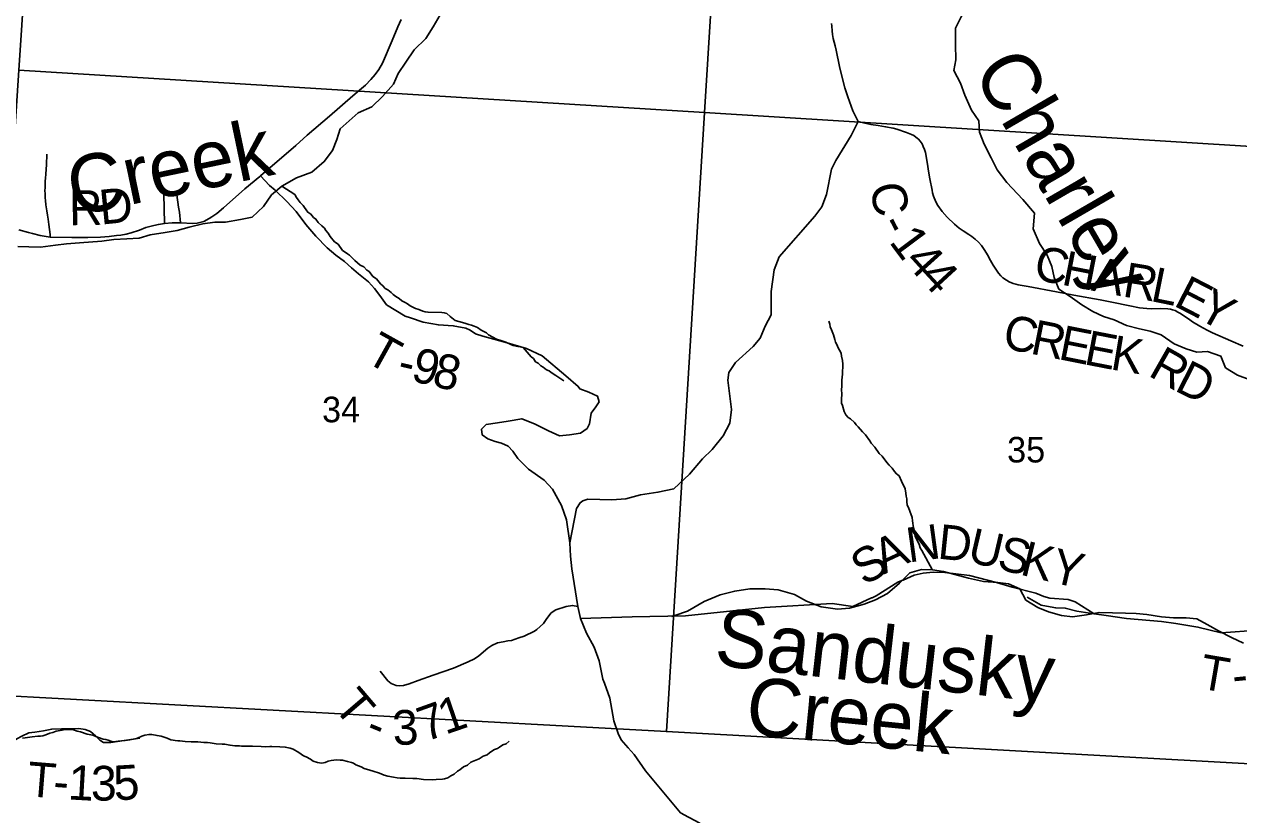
# Model space of a CAD drawing. Extents: x 0 to 45.4, y -2.2 to 22.
# Drawn here: x 5.991 to 7.977, y 14.939 to 16.232 of the extents above; entities that cross this region are included whole.
import ezdxf

# ---------------------------------------------------------------- set-up
doc = ezdxf.new("R2010")
doc.units = 0
for name, color, linetype in [('GM_X_Corporation', 7, 'Continuous'), ('GM_X_County_Road', 7, 'Continuous'), ('GM_X_County_Road_Text', 7, 'Continuous'), ('GM_X_Minor_River', 7, 'Continuous'), ('GM_X_Minor_River_Text', 7, 'Continuous'), ('GM_X_Section_Text', 7, 'Continuous'), ('GM_X_Township_Road', 7, 'Continuous'), ('GM_X_Township_Road_Text', 7, 'Continuous')]:
    doc.layers.add(name, color=color, linetype=linetype)

msp = doc.modelspace()

# ---------------------------------------------------------------- linework, layer by layer
at = {"layer": 'GM_X_Corporation'}
for points in [[(7.1661, 17.098), (7.1036, 16.0876), (5.9818, 16.1569), (6.0488, 17.1677)], [(8.2701, 17.0306), (8.2164, 16.0186), (7.1036, 16.0876), (7.1661, 17.098)], [(5.9818, 16.1569), (7.1036, 16.0876), (7.0412, 15.0748), (5.9148, 15.1362)], [(7.1036, 16.0876), (8.2164, 16.0186), (8.1634, 15.0131), (7.0412, 15.0748)]]:
    msp.add_lwpolyline(points, close=True, dxfattribs=at)
at = {"layer": 'GM_X_County_Road'}
for points in [[(6.2975, 15.9171), (6.3056, 15.9228), (6.3168, 15.9317), (6.3514, 15.9628), (6.3761, 15.9833), (6.3771, 15.9842), (6.4348, 16.0336), (6.4533, 16.0505), (6.4903, 16.082), (6.5283, 16.1148), (6.5393, 16.1242), (6.5488, 16.1326), (6.5575, 16.1417), (6.5646, 16.1498), (6.5707, 16.1582), (6.5766, 16.1686), (6.5927, 16.2054), (6.602, 16.228), (6.6071, 16.24)], [(7.3546, 16.0733), (7.346, 16.0904), (7.3377, 16.1136), (7.333, 16.1284), (7.3286, 16.1453), (7.3244, 16.1628), (7.3185, 16.1899), (7.317, 16.1971), (7.3141, 16.2086), (7.3129, 16.2154), (7.3123, 16.2215), (7.3117, 16.2292), (7.3111, 16.2332)], [(6.9396, 15.1541), (6.9373, 15.1605), (6.9313, 15.1908), (6.9232, 15.2131), (6.9105, 15.2359), (6.9004, 15.2597), (6.896, 15.2794), (6.8867, 15.3412), (6.884, 15.3617), (6.883, 15.3839), (6.8943, 15.4397), (6.9003, 15.4493), (6.9046, 15.4523), (6.9126, 15.455), (6.9516, 15.4543), (6.9748, 15.4558), (6.9989, 15.4624), (7.0273, 15.4666), (7.053, 15.4719), (7.0788, 15.4962), (7.1, 15.5209), (7.1159, 15.5364), (7.1341, 15.5588), (7.1447, 15.5793), (7.1478, 15.6021), (7.1417, 15.65), (7.1432, 15.6622), (7.1542, 15.6789), (7.183, 15.7051), (7.1943, 15.7188), (7.2027, 15.7382), (7.2122, 15.7568), (7.2122, 15.7948), (7.2171, 15.8305), (7.2258, 15.8514), (7.2837, 15.9181), (7.2952, 15.9337), (7.303, 15.9535), (7.3113, 15.9951), (7.3181, 16.0092), (7.3432, 16.0501), (7.3546, 16.0733)], [(7.3546, 16.0733), (7.3636, 16.0708), (7.3755, 16.068), (7.3875, 16.0665), (7.3997, 16.0645), (7.4121, 16.0621), (7.4181, 16.0605), (7.4339, 16.0553), (7.4417, 16.052), (7.4457, 16.05), (7.4492, 16.0474), (7.4532, 16.0441), (7.4561, 16.0409), (7.4596, 16.0363), (7.4613, 16.0324), (7.4635, 16.0272), (7.4649, 16.0223), (7.4681, 16.0032), (7.4699, 15.9918), (7.472, 15.9791), (7.4755, 15.9608), (7.4765, 15.9566), (7.478, 15.9509), (7.4818, 15.9417), (7.4851, 15.9355), (7.4921, 15.9259), (7.5004, 15.9165), (7.5121, 15.9051), (7.52, 15.8986), (7.5263, 15.8944), (7.5357, 15.8881), (7.5408, 15.8847), (7.5463, 15.8804), (7.5514, 15.8755), (7.5566, 15.8703), (7.562, 15.8621), (7.566, 15.8547), (7.5712, 15.8459), (7.5758, 15.8381), (7.5798, 15.8313), (7.5845, 15.8247), (7.5882, 15.8207), (7.5915, 15.8174)], [(5.9819, 15.8958), (5.9976, 15.8914), (6.0044, 15.8896), (6.0167, 15.8865), (6.0334, 15.8838), (6.0685, 15.8831), (6.0781, 15.8831), (6.0951, 15.8835), (6.1153, 15.884), (6.1299, 15.8851), (6.1417, 15.8863), (6.1489, 15.8873), (6.1573, 15.8889), (6.1658, 15.891), (6.1791, 15.8954), (6.1898, 15.8995), (6.196, 15.9012), (6.2029, 15.9029), (6.2104, 15.9046), (6.2204, 15.9061), (6.233, 15.9074), (6.2465, 15.9072), (6.2665, 15.9063), (6.2736, 15.9067), (6.2846, 15.9094), (6.2935, 15.9142), (6.2975, 15.9171)], [(7.5915, 15.8174), (7.5976, 15.8133), (7.6019, 15.8106), (7.608, 15.8082), (7.6128, 15.807)], [(7.6128, 15.807), (7.6166, 15.806), (7.633, 15.803), (7.6793, 15.7943), (7.7074, 15.7892), (7.7505, 15.7813), (7.7696, 15.7777), (7.7993, 15.7715), (7.8147, 15.7683), (7.8268, 15.7671), (7.8346, 15.7668), (7.8494, 15.767), (7.8611, 15.7666), (7.8656, 15.7661), (7.869, 15.7652), (7.8734, 15.7637), (7.8778, 15.7614), (7.882, 15.7587), (7.897, 15.7486), (7.9018, 15.7454), (7.9138, 15.7383), (7.9258, 15.7316), (7.9343, 15.7274), (7.9644, 15.7141), (7.9844, 15.7055)], [(7.2323, 14.6533), (7.2219, 14.6911), (7.2115, 14.7136), (7.1903, 14.7423), (7.169, 14.7705), (7.1488, 14.7944), (7.1219, 14.8551), (7.1121, 14.8973), (7.109, 14.909), (7.1011, 14.9216), (7.0886, 14.9288), (7.0772, 14.9349), (7.064, 14.9421), (7.0068, 15.0105), (6.9882, 15.0375), (6.9785, 15.0483), (6.9672, 15.0617), (6.9622, 15.0719), (6.9553, 15.0924), (6.9485, 15.1296), (6.9396, 15.1541)]]:
    msp.add_lwpolyline(points, dxfattribs=at)
at = {"layer": 'GM_X_Minor_River'}
for points in [[(7.5145, 16.1739), (7.5139, 16.199), (7.514, 16.2256), (7.5239, 16.2453), (7.5346, 16.2628), (7.5399, 16.2833), (7.5423, 16.3023), (7.5469, 16.3236), (7.5538, 16.3418), (7.544, 16.3601), (7.5267, 16.3724), (7.5085, 16.3884), (7.4912, 16.3999), (7.4753, 16.4144)], [(5.9803, 15.8686), (5.9985, 15.8678), (6.0174, 15.8677), (6.0417, 15.8706), (6.0599, 15.8729), (6.0811, 15.8743), (6.1175, 15.8772), (6.1372, 15.8802), (6.1584, 15.8809), (6.1788, 15.8823), (6.197, 15.8876), (6.2213, 15.8913), (6.241, 15.895), (6.2607, 15.9002), (6.2827, 15.9055), (6.3024, 15.9084), (6.3198, 15.9084), (6.3448, 15.9129), (6.3638, 15.9166), (6.382, 15.934), (6.395, 15.953), (6.4124, 15.9673), (6.436, 15.9809), (6.461, 15.99), (6.4815, 16.0074), (6.4952, 16.0256), (6.5021, 16.0438), (6.5075, 16.0613), (6.5371, 16.087), (6.5591, 16.0968), (6.5766, 16.1142), (6.5949, 16.1339), (6.6025, 16.1514), (6.6147, 16.1704), (6.6284, 16.1901), (6.6475, 16.209), (6.6596, 16.228), (6.6711, 16.2477)], [(7.9941, 15.6511), (7.9752, 15.658), (7.9556, 15.6703), (7.9481, 15.6893), (7.9261, 15.697), (7.9087, 15.6955), (7.8913, 15.7009), (7.8717, 15.7094), (7.8505, 15.7239), (7.8324, 15.73), (7.815, 15.7339), (7.7938, 15.7393), (7.7734, 15.7485), (7.756, 15.7539), (7.7386, 15.7623), (7.7204, 15.7731), (7.7016, 15.7868), (7.6827, 15.799), (7.6752, 15.8181), (7.6715, 15.8356), (7.664, 15.8546), (7.6512, 15.8737), (7.6407, 15.8973), (7.643, 15.9231), (7.6242, 15.9453), (7.5978, 15.9735), (7.582, 15.9941), (7.5722, 16.0139), (7.5609, 16.036), (7.5534, 16.0558), (7.552, 16.0741), (7.5399, 16.0916), (7.5294, 16.116), (7.5219, 16.1358), (7.5114, 16.1564), (7.5145, 16.1739)], [(6.4124, 15.9673), (6.4335, 15.9536), (6.436, 15.949), (6.439, 15.9448), (6.4423, 15.9405), (6.4468, 15.9359), (6.4494, 15.9324), (6.4546, 15.9247), (6.4598, 15.9216), (6.4642, 15.9158), (6.468, 15.9135), (6.4717, 15.9077), (6.4776, 15.9023), (6.4817, 15.8984), (6.484, 15.895), (6.488, 15.8903), (6.4914, 15.8849), (6.4984, 15.8761), (6.504, 15.8722), (6.5114, 15.8622), (6.5155, 15.8594), (6.5193, 15.8563), (6.5226, 15.8544), (6.5282, 15.8489), (6.5316, 15.8458), (6.5405, 15.8381), (6.5462, 15.8353), (6.5514, 15.8299), (6.5551, 15.8276), (6.5607, 15.8195), (6.567, 15.8156), (6.5733, 15.8075), (6.5775, 15.8044), (6.5812, 15.8001), (6.5857, 15.7974), (6.5909, 15.7935), (6.5943, 15.79), (6.5984, 15.7865), (6.604, 15.7834), (6.6085, 15.7795), (6.6141, 15.7768), (6.6179, 15.7748), (6.6223, 15.7713), (6.631, 15.767), (6.6344, 15.7658), (6.6389, 15.7645), (6.643, 15.7629), (6.6464, 15.7618), (6.6513, 15.7609), (6.674, 15.7605), (6.6778, 15.7601), (6.682, 15.7589), (6.6876, 15.7542), (6.6958, 15.7476), (6.7018, 15.7456), (6.7116, 15.7431), (6.718, 15.7411), (6.7222, 15.7399), (6.7267, 15.7383), (6.732, 15.7359), (6.7383, 15.7317), (6.747, 15.7273), (6.7503, 15.7242), (6.7631, 15.7172), (6.7721, 15.7143), (6.7785, 15.712), (6.7864, 15.708), (6.7905, 15.7068), (6.7981, 15.7052), (6.8022, 15.7043), (6.8068, 15.7035), (6.8134, 15.6958), (6.8201, 15.688), (6.8235, 15.6853), (6.8272, 15.6799), (6.8313, 15.6776), (6.8358, 15.6733), (6.8395, 15.671), (6.8451, 15.6667), (6.8493, 15.6651), (6.8526, 15.6624), (6.8605, 15.6573), (6.8654, 15.6542), (6.8732, 15.6489)], [(7.4759, 15.34), (7.4589, 15.3714), (7.4563, 15.3757), (7.4546, 15.3814), (7.452, 15.3864), (7.448, 15.3948), (7.4469, 15.4002), (7.4466, 15.4047), (7.4445, 15.4116), (7.4442, 15.4158), (7.4435, 15.4196), (7.4428, 15.4253), (7.4392, 15.4353), (7.437, 15.4414), (7.4348, 15.4456), (7.4346, 15.4513), (7.4343, 15.4559), (7.4332, 15.4601), (7.4325, 15.465), (7.4315, 15.4722), (7.4257, 15.4845), (7.4217, 15.4933), (7.4172, 15.4968), (7.4142, 15.5007), (7.4101, 15.5061), (7.4057, 15.5107), (7.4016, 15.5153), (7.3942, 15.5253), (7.3893, 15.53), (7.382, 15.5404), (7.376, 15.5466), (7.3738, 15.5508), (7.3668, 15.5604), (7.3619, 15.5651), (7.3549, 15.5735), (7.3515, 15.5766), (7.3486, 15.5805), (7.3422, 15.5867), (7.3385, 15.589), (7.3344, 15.5933), (7.3318, 15.5986), (7.3293, 15.6082), (7.3275, 15.6124), (7.3276, 15.6189), (7.3278, 15.6272), (7.3275, 15.6345), (7.328, 15.6394), (7.3282, 15.65), (7.3291, 15.6595), (7.3294, 15.6762), (7.3291, 15.682), (7.3277, 15.6892), (7.3267, 15.6942), (7.3241, 15.6988), (7.3219, 15.7026), (7.3197, 15.7084), (7.3175, 15.7122), (7.3165, 15.7164), (7.3143, 15.724), (7.3114, 15.7321), (7.3092, 15.7371), (7.3082, 15.7416), (7.3068, 15.7462)], [(7.9848, 15.2196), (7.9651, 15.2288), (7.944, 15.2395), (7.9258, 15.2502), (7.9085, 15.2594), (7.8911, 15.261), (7.8706, 15.261), (7.8509, 15.2626), (7.8267, 15.2665), (7.8093, 15.2681), (7.7919, 15.2689), (7.7707, 15.269), (7.7487, 15.2699), (7.7282, 15.2661), (7.7055, 15.2624), (7.6873, 15.2648), (7.6662, 15.2709), (7.6488, 15.2778), (7.6291, 15.2901), (7.6194, 15.3083), (7.6005, 15.3168), (7.583, 15.3191), (7.5596, 15.3207), (7.5354, 15.3261), (7.4945, 15.3369), (7.4763, 15.3393), (7.4582, 15.3401), (7.4392, 15.3349), (7.4225, 15.3175), (7.4027, 15.3008), (7.383, 15.2903), (7.3648, 15.2835), (7.3405, 15.2767), (7.3208, 15.2753), (7.2943, 15.2792), (7.2701, 15.2884), (7.2505, 15.2991), (7.224, 15.3068), (7.2028, 15.3084), (7.1778, 15.3085), (7.1528, 15.3048), (7.1293, 15.2988), (7.1027, 15.2875), (7.0754, 15.2717), (7.0549, 15.2649), (7.0496, 15.2634)], [(5.988, 15.0642), (5.9925, 15.0649), (6.0039, 15.0662), (6.013, 15.0672), (6.0176, 15.0675), (6.0214, 15.0682), (6.026, 15.0696), (6.0328, 15.0722), (6.0378, 15.0736), (6.0431, 15.0758), (6.0526, 15.0775), (6.0579, 15.0782), (6.0625, 15.0781), (6.0712, 15.0776), (6.0776, 15.0756), (6.0829, 15.0744), (6.0938, 15.0707), (6.1032, 15.0691), (6.1077, 15.0667), (6.1198, 15.0627), (6.1243, 15.0619), (6.1281, 15.061), (6.1322, 15.0591), (6.1364, 15.0579), (6.1447, 15.0592), (6.1497, 15.0599), (6.1561, 15.0606), (6.1633, 15.0612), (6.1724, 15.0633), (6.1763, 15.0644), (6.1831, 15.0677), (6.1881, 15.0688), (6.1949, 15.0702), (6.1995, 15.0701), (6.2081, 15.0684), (6.2149, 15.0672), (6.2244, 15.0643), (6.2304, 15.0612), (6.2345, 15.0607), (6.2379, 15.0603), (6.2421, 15.0599), (6.2455, 15.0598), (6.2538, 15.0589), (6.264, 15.0583), (6.2678, 15.0579), (6.275, 15.0582), (6.2845, 15.0572), (6.2905, 15.0568), (6.2947, 15.0563), (6.3049, 15.055), (6.3143, 15.0544), (6.3185, 15.0544), (6.3276, 15.0527), (6.3355, 15.0518), (6.3427, 15.0517), (6.3461, 15.0512), (6.3571, 15.0511), (6.3639, 15.0509), (6.3783, 15.0503), (6.3851, 15.0502), (6.3923, 15.0508), (6.3957, 15.0508), (6.4086, 15.0502), (6.4177, 15.0496), (6.4256, 15.0476), (6.4305, 15.046), (6.4402, 15.0409)], [(6.4402, 15.0409), (6.4477, 15.0355), (6.4519, 15.0335), (6.459, 15.0296), (6.4635, 15.0268), (6.4706, 15.0244), (6.474, 15.0236), (6.4774, 15.0232), (6.4828, 15.0246), (6.4877, 15.0268), (6.493, 15.0275), (6.5014, 15.0285), (6.5078, 15.0283), (6.5116, 15.0279), (6.5195, 15.0262), (6.5259, 15.0246), (6.5293, 15.023), (6.5331, 15.0203), (6.5417, 15.0175), (6.5466, 15.0144), (6.556, 15.0119), (6.5617, 15.0099), (6.5719, 15.0067), (6.5794, 15.0036), (6.5854, 15.0019), (6.5945, 15.0006), (6.6005, 14.9994), (6.6058, 14.9986), (6.6141, 14.9988), (6.6262, 14.9982), (6.6331, 14.9981), (6.644, 14.9964), (6.6588, 14.9961), (6.6645, 14.9968), (6.6747, 14.997), (6.6781, 14.9977), (6.6838, 14.9995), (6.6884, 15.0025), (6.6942, 15.005), (6.6996, 15.0102), (6.703, 15.0125), (6.7095, 15.0173), (6.7156, 15.0202), (6.721, 15.0247), (6.7351, 15.0305), (6.7413, 15.0346), (6.7478, 15.0371), (6.7516, 15.0401), (6.7554, 15.0427), (6.76, 15.0457), (6.7646, 15.0475), (6.7684, 15.0497), (6.7738, 15.053), (6.7791, 15.0548), (6.7841, 15.0593)]]:
    msp.add_lwpolyline(points, dxfattribs=at)
at = {"layer": 'GM_X_Township_Road'}
msp.add_line((6.2204, 15.9061), (6.219, 15.9549), dxfattribs=at)
for points in [[(6.0334, 15.8838), (6.033, 15.8881), (6.0309, 15.9043), (6.0298, 15.9131), (6.0288, 15.9201), (6.0278, 15.927), (6.0263, 15.9366), (6.0255, 15.9439), (6.0253, 15.948), (6.0248, 15.9555), (6.0246, 15.9594), (6.0248, 15.9653), (6.0249, 15.97), (6.0252, 15.9758), (6.0255, 15.9797), (6.0261, 15.9877), (6.0271, 16.002), (6.028, 16.0196)], [(6.883, 15.3839), (6.8777, 15.4216), (6.8697, 15.4447), (6.8546, 15.4717), (6.841, 15.4862), (6.8156, 15.5041), (6.7979, 15.5219), (6.79, 15.5338), (6.7821, 15.5418), (6.7715, 15.547), (6.7609, 15.5497), (6.7491, 15.5537), (6.7398, 15.5603), (6.7385, 15.5695), (6.7464, 15.5774), (6.7649, 15.58), (6.7821, 15.5827), (6.8045, 15.5867), (6.8256, 15.5787), (6.8481, 15.5668), (6.8665, 15.5589), (6.8824, 15.5602), (6.9008, 15.5629), (6.9114, 15.5708), (6.9154, 15.5787), (6.918, 15.5959), (6.9259, 15.6064), (6.9312, 15.6144), (6.9286, 15.6236), (6.914, 15.6302), (6.8995, 15.6355), (6.897, 15.6397), (6.8766, 15.6568), (6.8379, 15.6898), (6.8124, 15.7019), (6.7808, 15.7109), (6.7411, 15.7221), (6.7289, 15.7255), (6.7204, 15.7316), (6.713, 15.7351), (6.6925, 15.739), (6.6682, 15.7404), (6.6434, 15.7448), (6.6225, 15.7517), (6.6137, 15.7546), (6.5832, 15.7733), (6.5725, 15.7886), (6.5636, 15.7999), (6.554, 15.8105), (6.5375, 15.8241), (6.5263, 15.8334), (6.5145, 15.8438), (6.5003, 15.8546), (6.4861, 15.8665), (6.4678, 15.8857), (6.4514, 15.9047), (6.4357, 15.9258), (6.4201, 15.9422), (6.4014, 15.9605), (6.3921, 15.9681), (6.3771, 15.9842)], [(6.2465, 15.9072), (6.2449, 15.925), (6.2433, 15.933), (6.2404, 15.9531)], [(7.8744, 15.2515), (7.8511, 15.2551), (7.7937, 15.26), (7.7606, 15.2646), (7.7408, 15.2677), (7.7095, 15.2874), (7.6984, 15.2909), (7.6683, 15.2931), (7.6584, 15.2961), (7.6451, 15.3016), (7.6067, 15.3113), (7.5809, 15.3189), (7.5367, 15.3302), (7.4964, 15.3351), (7.4775, 15.3356), (7.4608, 15.3341), (7.4464, 15.331), (7.4281, 15.3229)], [(7.4281, 15.3229), (7.4263, 15.3221), (7.4195, 15.3194), (7.3844, 15.297), (7.3774, 15.2939)], [(7.631, 15.2951), (7.6538, 15.2816), (7.6565, 15.2811)], [(6.5728, 15.1737), (6.5853, 15.1582), (6.5909, 15.1537), (6.5992, 15.1504), (6.6045, 15.15), (6.6111, 15.1506), (6.6202, 15.1532), (6.6351, 15.1587), (6.6597, 15.1675), (6.693, 15.1788), (6.717, 15.1891), (6.7272, 15.1939), (6.7343, 15.1987), (6.7489, 15.2114), (6.7556, 15.216), (6.7648, 15.22), (6.7742, 15.222), (6.7818, 15.2235), (6.7877, 15.2237), (6.7999, 15.2281), (6.8085, 15.2313), (6.8255, 15.2393), (6.8293, 15.2419), (6.8399, 15.2515), (6.8457, 15.2598), (6.8527, 15.2691), (6.8601, 15.2742), (6.877, 15.2794), (6.8873, 15.2813), (6.896, 15.2794)], [(7.3774, 15.2939), (7.3765, 15.2935), (7.3458, 15.2797), (7.3123, 15.2846), (7.2017, 15.2781), (7.0725, 15.2642), (6.9852, 15.2625), (6.9004, 15.2597)], [(7.6565, 15.2811), (7.678, 15.2773), (7.6934, 15.2769), (7.7125, 15.2717), (7.7408, 15.2677)], [(8.0088, 15.2409), (7.9485, 15.2364), (7.9105, 15.246), (7.8744, 15.2515)], [(5.937, 15.0459), (5.9388, 15.0458), (5.9483, 15.0454), (5.9577, 15.048), (5.9654, 15.0527), (5.9788, 15.0629), (5.9868, 15.0675), (5.9985, 15.0729), (6.0083, 15.074), (6.0225, 15.0762), (6.0358, 15.0791), (6.0516, 15.0793), (6.0671, 15.0795), (6.08, 15.08), (6.0904, 15.0783), (6.0993, 15.0749), (6.1077, 15.0675), (6.1142, 15.0611), (6.1204, 15.0573), (6.1326, 15.0571), (6.1801, 15.0639)]]:
    msp.add_lwpolyline(points, dxfattribs=at)

# ---------------------------------------------------------------- texts
at = {"layer": 'GM_X_County_Road_Text'}
for s, rotation, p in [('C', 281.0116, (7.3734, 15.9679)), ('R', 0.8443, (6.0644, 15.9033)), ('D', 5.6492, (6.1162, 15.9043)), ('-', 297.482, (7.3881, 15.9053)), ('1', 306.6969, (7.4042, 15.8761)), ('4', 312.074, (7.4288, 15.8436)), ('C', 348.9598, (7.6398, 15.8153)), ('H', 348.9613, (7.6856, 15.8064)), ('4', 312.6817, (7.4527, 15.8171)), ('A', 349.0826, (7.7348, 15.7968)), ('R', 350.7598, (7.7857, 15.787)), ('L', 348.625, (7.8312, 15.7796)), ('E', 332.6884, (7.8689, 15.7726)), ('Y', 330.5426, (7.9062, 15.7533)), ('C', 348.7522, (7.5889, 15.7027)), ('R', 348.7573, (7.6346, 15.6936)), ('E', 348.8095, (7.6805, 15.6845)), ('E', 349.0241, (7.7224, 15.6762)), ('K', 350.5196, (7.7657, 15.6678)), ('R', 330.4794, (7.8273, 15.6582)), ('D', 333.0207, (7.8703, 15.6339))]:
    msp.add_text(s, height=0.0568, rotation=rotation, dxfattribs=at).set_placement(p)
at = {"layer": 'GM_X_Minor_River_Text'}
for s, height, rotation, p in [('Charley', 0.09482, 300.1349, (7.5405, 16.1556)), ('Creek', 0.0947, 11.8017, (6.0725, 15.9175)), ('Sandusky', 0.0947, 353.5222, (7.1175, 15.184)), ('Creek', 0.0947, 354.2984, (7.1683, 15.0712))]:
    msp.add_text(s, height=height, rotation=rotation, dxfattribs=at).set_placement(p)
at = {"layer": 'GM_X_Section_Text'}
for s, p in [('34', (6.4779, 15.581)), ('35', (7.5983, 15.5152))]:
    msp.add_text(s, height=0.04186, rotation=0, dxfattribs=at).set_placement(p)
at = {"layer": 'GM_X_Township_Road_Text'}
for s, rotation, p in [('T', 330.9661, (6.5458, 15.6815)), ('9', 346.1881, (6.6213, 15.6494)), ('8', 346.664, (6.6558, 15.6409)), ('-', 346.6821, (6.5987, 15.6547)), ('N', 7.7095, (7.4374, 15.3515)), ('D', 354.0919, (7.4834, 15.3581)), ('A', 25.0376, (7.3964, 15.3316)), ('U', 346.897, (7.5313, 15.3533)), ('S', 345.3553, (7.5796, 15.342)), ('S', 31.0386, (7.365, 15.3125)), ('K', 346.404, (7.6178, 15.3321)), ('Y', 347.008, (7.667, 15.3202)), ('T', 350.2894, (7.9106, 15.146)), ('-', 5.4829, (7.9689, 15.1383)), ('T', 310.5121, (6.4946, 15.1149)), ('7', 19.6877, (6.6467, 15.0578)), ('1', 18.9887, (6.6795, 15.0696)), ('3', 3.5534, (6.5947, 15.0522)), ('-', 337.6153, (6.5457, 15.0656)), ('T', 355.3396, (5.9942, 14.9694)), ('1', 356.8641, (6.0615, 14.964)), ('3', 0.0586, (6.0999, 14.962)), ('5', 3.3701, (6.1384, 14.9622)), ('-', 355.6943, (6.0369, 14.9659))]:
    msp.add_text(s, height=0.0568, rotation=rotation, dxfattribs=at).set_placement(p)

doc.saveas('drawing.dxf')
